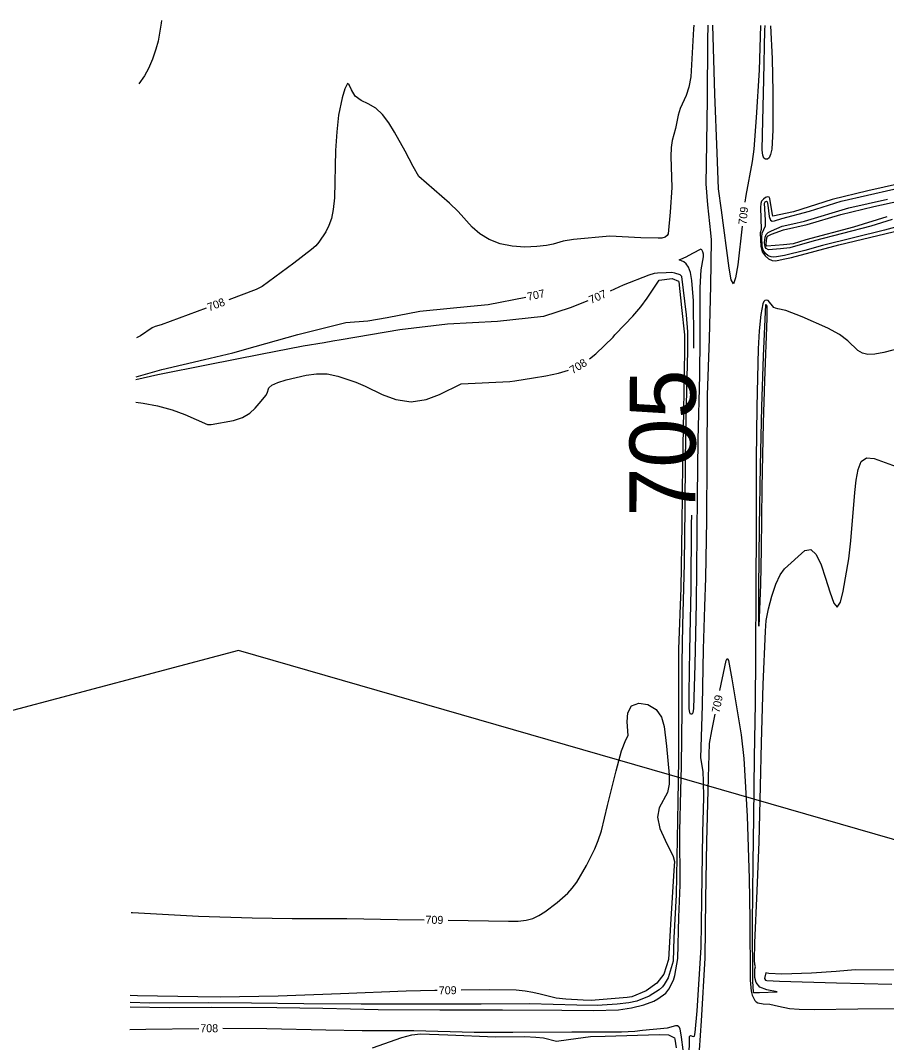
# Model space of a CAD drawing. Extents: x -468548933 to 3387700, y -306089263 to 1207014.
# Drawn here: x 1840205 to 1840637, y 538847 to 539357 of the extents above; entities that cross this region are included whole.
import ezdxf

# ---------------------------------------------------------------- set-up
doc = ezdxf.new("R2010")
doc.units = 0
for name, color, linetype in [('DT_X_Contour_Minor', 7, 'Continuous'), ('Level 19', 7, 'Continuous'), ('SC_Scratch1', 7, 'Continuous')]:
    doc.layers.add(name, color=color, linetype=linetype)

msp = doc.modelspace()

# ---------------------------------------------------------------- linework, layer by layer
at = {"layer": 'DT_X_Contour_Minor'}
for points in [[(1840275.27, 539357.39), (1840275.11, 539356.02), (1840273.58, 539347.09), (1840272.42, 539342.95), (1840270.74, 539337.98), (1840268.79, 539333.3), (1840266.8, 539329.74), (1840263.84, 539325.63)], [(1840541.08, 539355.09), (1840540.95, 539353.22), (1840539.56, 539329.22), (1840538.65, 539323.96), (1840537.24, 539319.82), (1840534.2, 539313.32), (1840533.25, 539310.01), (1840531.95, 539303.42), (1840530.29, 539297.44), (1840529.71, 539293.82), (1840529.58, 539289.35), (1840530.14, 539273.93), (1840529.32, 539261.5), (1840528.18, 539250.74), (1840527.67, 539249.86), (1840526.82, 539249.16), (1840525.11, 539248.62), (1840523.21, 539248.51), (1840514.65, 539248.83), (1840499.15, 539249.59), (1840480.99, 539247.95), (1840475.79, 539247.08), (1840470.81, 539245.57), (1840467.46, 539244.97), (1840462.6, 539244.4), (1840456.7, 539244.14), (1840450.42, 539244.53), (1840444.36, 539245.83), (1840438.85, 539247.97), (1840434.17, 539250.77), (1840430.44, 539254.1), (1840423.45, 539261.89), (1840419, 539266.08), (1840403.75, 539279.32), (1840400.96, 539284.32), (1840396.95, 539292.04), (1840391.55, 539301.57), (1840388.68, 539306.2), (1840385.64, 539310.3), (1840382.26, 539313.51), (1840378.51, 539315.67), (1840374.87, 539317.43), (1840371.94, 539319.61), (1840370.12, 539322.63), (1840369.03, 539325.25), (1840368.07, 539325.82), (1840366.82, 539323.26), (1840365.45, 539318.72), (1840363.59, 539310.13), (1840362.71, 539301.77), (1840362.2, 539292.44), (1840361.62, 539268.81), (1840361.03, 539262.84), (1840360.12, 539258.39), (1840358.86, 539254.83), (1840357.28, 539251.67), (1840353.88, 539246.64), (1840352.31, 539244.83), (1840350.19, 539242.89), (1840341.39, 539236.05), (1840325.52, 539224.36), (1840322.51, 539222.97), (1840308.82, 539217.81)], [(1840538.51, 538827.07), (1840538.9, 538849.64), (1840539.44, 538850.12), (1840540.81, 538849.55), (1840541.33, 538849.84), (1840541.75, 538851.59), (1840542.7, 538862.52), (1840544.67, 538894.15), (1840545.01, 538918.11), (1840545.62, 538951.61), (1840546, 538969), (1840545.97, 538976.98), (1840545.68, 538982.02), (1840544.62, 538988.9), (1840545.32, 539015.05), (1840545.86, 539043.18), (1840546.54, 539064.45), (1840547.04, 539078.86), (1840547.49, 539107.66), (1840547.77, 539138.03), (1840547.94, 539170.04), (1840548.81, 539198.39), (1840549.51, 539224.79), (1840549.88, 539247.75), (1840549.63, 539251.26), (1840548.07, 539265.28), (1840547.29, 539275.69), (1840547.32, 539285.61), (1840547.91, 539318.1), (1840548.11, 539347.54), (1840548.17, 539355.03)], [(1840565.19, 539254.65), (1840563.03, 539235.2), (1840561.93, 539228.72), (1840560.82, 539225.81), (1840559.74, 539227.82), (1840558.7, 539233.61), (1840554.89, 539262.6), (1840553.39, 539273.19), (1840552.64, 539291.27), (1840551.61, 539320.52), (1840550.6, 539355.01)], [(1840574.38, 539354.81), (1840573.69, 539332.46), (1840572.24, 539308.84), (1840571.04, 539293), (1840570.16, 539286.89), (1840566.97, 539269.97), (1840566.57, 539266.57)], [(1840579.32, 539354.76), (1840580.17, 539338.36), (1840580.53, 539321.56), (1840580.49, 539302.51), (1840579.98, 539293.1), (1840579.42, 539290.32), (1840578.69, 539288.8), (1840577.83, 539288.14), (1840576.92, 539288.05), (1840576.09, 539288.62), (1840575.49, 539290.07), (1840575.22, 539292.56), (1840575.32, 539300.46), (1840575.98, 539327.83), (1840576.59, 539352.53), (1840576.65, 539354.79)], [(1840652.47, 539277.8), (1840627.95, 539272.26), (1840610.13, 539267.92), (1840590.92, 539261.81), (1840580.47, 539259.64), (1840580.11, 539261.19), (1840579.08, 539268.33), (1840578.63, 539269.02), (1840577.92, 539269.2), (1840576.92, 539268.84), (1840575.83, 539268.07), (1840574.94, 539267.06), (1840574.45, 539265.96), (1840574.3, 539263.85), (1840574.67, 539252.92), (1840574.26, 539251.27), (1840574.28, 539247.52), (1840574.54, 539244.61), (1840575.27, 539241.82), (1840576.61, 539239.67), (1840578.36, 539238.24), (1840580.26, 539237.48), (1840582.05, 539237.32), (1840585.6, 539238.02), (1840589.78, 539239), (1840613.46, 539245.3), (1840644.74, 539252.76)], [(1840643.63, 539254.53), (1840636.34, 539252.58), (1840605.24, 539244.99), (1840596.46, 539242.47), (1840586.26, 539239.91), (1840582.33, 539239.28), (1840581.04, 539239.12), (1840579.64, 539239.25), (1840578.16, 539239.83), (1840576.8, 539240.94), (1840575.76, 539242.62), (1840575.19, 539244.79), (1840574.98, 539249.03), (1840575.13, 539251), (1840576.92, 539254.68), (1840576.83, 539257.58), (1840576.28, 539266.04), (1840576.69, 539266.73), (1840577.33, 539267.07), (1840577.68, 539266.81), (1840577.95, 539265.11), (1840578.76, 539259.33), (1840579.37, 539257.66), (1840580.23, 539257.06), (1840581.42, 539257.27), (1840584.98, 539258.47), (1840598.87, 539262.13), (1840614.59, 539266.99), (1840640.97, 539273.05)], [(1840640.05, 539257.86), (1840629.43, 539254.62), (1840601.21, 539247.32), (1840588.94, 539243.81), (1840584.27, 539243.28), (1840578.4, 539242.77), (1840577.18, 539243.5), (1840576.74, 539244.21), (1840576.42, 539246.23), (1840576.64, 539249.09), (1840577.2, 539250.43), (1840578.12, 539251.38), (1840579.83, 539252.22), (1840582.53, 539253.42), (1840585.17, 539254.58), (1840590.56, 539255.73), (1840596.36, 539257.11), (1840618.54, 539263.67), (1840637.79, 539268.09)], [(1840637.51, 539259.3), (1840620.72, 539254.15), (1840596.98, 539247.76), (1840590.6, 539245.81), (1840585.92, 539245.2), (1840577.57, 539244.62), (1840577.23, 539245.01), (1840577.13, 539245.8), (1840577.49, 539248.83), (1840577.91, 539249.63), (1840579.91, 539250.59), (1840585.88, 539252.8), (1840597.73, 539255.4), (1840614.53, 539260.48), (1840630.95, 539264.45), (1840643.96, 539267.23)], [(1840541.09, 539193.54), (1840541.11, 539198.23), (1840540.85, 539217.32), (1840540.07, 539227.39), (1840539.39, 539231.38), (1840538.43, 539234.14), (1840537.28, 539235.79), (1840536.07, 539236.7), (1840533.75, 539237.7), (1840534.62, 539238.16), (1840537.19, 539239.24), (1840540.62, 539241.06), (1840544.77, 539243.29), (1840545.4, 539241.9), (1840545.72, 539240.67), (1840545.8, 539239.28), (1840544.48, 539232.83), (1840544.1, 539223.92), (1840544.05, 539198.53), (1840543.83, 539180.17), (1840543.03, 539147.81), (1840542.73, 539119.66), (1840542.36, 539082.95), (1840542.18, 539066.32), (1840541.54, 539035.4), (1840540.91, 539013.5), (1840540.6, 539011.42), (1840540.22, 539010.66), (1840539.41, 539010.67), (1840539.05, 539011.43), (1840538.81, 539013.47), (1840538.74, 539021.39), (1840539.12, 539042.7), (1840539.66, 539073.16), (1840539.98, 539105.62), (1840539.99, 539110.23)], [(1840259.57, 538864.53), (1840279.11, 538864.1), (1840300.18, 538864.22), (1840332.91, 538864.04), (1840355.72, 538863.76), (1840383.5, 538863.11), (1840414.26, 538862.97), (1840445.56, 538862.89), (1840475.22, 538862.86), (1840490.97, 538862.62), (1840503.5, 538863.03), (1840509.98, 538863.93), (1840516.03, 538865.45), (1840521.05, 538867.27), (1840523.16, 538868.4), (1840527.1, 538871.36), (1840528.59, 538873.24), (1840530.93, 538877.72), (1840531.59, 538880.03), (1840533.12, 538888.58), (1840533.54, 538909.31), (1840534.25, 538925.28), (1840534.06, 538952.25), (1840534.65, 538972.49), (1840534.94, 538984.74), (1840535.26, 539012.92), (1840535.26, 539036.23), (1840535.61, 539055.22), (1840536.46, 539085.95), (1840536.76, 539113.5), (1840536.98, 539138.7), (1840537.47, 539165.37), (1840538.02, 539192.32), (1840538.01, 539201.84), (1840537.4, 539210.32), (1840535.11, 539229.37), (1840534.24, 539230.28), (1840531.52, 539231.17), (1840530.12, 539231.44), (1840527.24, 539231.27), (1840522.96, 539231.04), (1840521.19, 539230.95), (1840518.63, 539230.11), (1840505.8, 539225.04), (1840499.21, 539222.09)], [(1840488.99, 539188.27), (1840492.11, 539190.75), (1840500.84, 539199.04), (1840501.66, 539200.32), (1840506.53, 539205.48), (1840510.53, 539209.66), (1840514.53, 539214.24), (1840517.83, 539218.68), (1840523.68, 539227.66), (1840530.22, 539228.35), (1840533.42, 539227.03), (1840533.51, 539226.73), (1840534.92, 539214), (1840536.47, 539200.28), (1840536.48, 539192.29), (1840535.85, 539162.33), (1840535.42, 539136.08), (1840535.05, 539105.52), (1840534.52, 539073.76), (1840533.43, 539043.19), (1840533.43, 539018.18), (1840533.34, 538988.19), (1840533.05, 538966.99), (1840532.74, 538948.36), (1840532.21, 538920.34), (1840531.12, 538898.92), (1840530.72, 538887.2), (1840528.25, 538878.89), (1840526.31, 538875.69), (1840525.44, 538874.37), (1840523.73, 538872.87), (1840518.68, 538869.7), (1840512.57, 538867.36), (1840508.6, 538866.44), (1840502.81, 538865.81), (1840492.8, 538865.12), (1840482.63, 538865.23), (1840459.01, 538865.89), (1840434.85, 538865.81), (1840407.62, 538865.77), (1840375.02, 538865.72), (1840346.31, 538865.99), (1840320.16, 538866.33), (1840298.85, 538866.52), (1840269.49, 538866.21), (1840259.59, 538866.55)], [(1840488.21, 539217.28), (1840479.28, 539213.85), (1840465.97, 539209.45), (1840443.01, 539206.88), (1840418.12, 539205.68), (1840394.27, 539202.7), (1840364.88, 539197.82), (1840360.79, 539197.05), (1840356.44, 539196.26), (1840345.96, 539194.57), (1840324.59, 539190.42), (1840298.54, 539185.35), (1840273.39, 539180.36), (1840262.48, 539177.72)], [(1840262.5, 539179.22), (1840275.44, 539182.96), (1840296.72, 539188.01), (1840310.81, 539191.34), (1840321.99, 539194.41), (1840343.33, 539200.45), (1840367.27, 539206.37), (1840378.25, 539207.33), (1840387.98, 539208.97), (1840404.28, 539212.15), (1840405.84, 539212.34), (1840429.48, 539214.61), (1840438.36, 539215.48), (1840457.11, 539219.16)], [(1840648.82, 539194.75), (1840635.93, 539191.42), (1840631.41, 539190.59), (1840627.91, 539190.46), (1840625.24, 539191.1), (1840623.03, 539192.51), (1840617.99, 539197.35), (1840613.82, 539200.41), (1840607.94, 539203.61), (1840595.1, 539209.25), (1840587.01, 539212.38), (1840582.99, 539213.35), (1840581.82, 539213.53), (1840580.96, 539213.95), (1840578.14, 539217.4), (1840577.31, 539217.53), (1840576.57, 539217.35), (1840575.99, 539216.87), (1840575.53, 539215.79), (1840574.6, 539210.45), (1840573.73, 539202.26), (1840573.24, 539193.28), (1840572.54, 539164.32), (1840572.14, 539137.98), (1840572.14, 539103.4), (1840571.99, 539074.52), (1840571.8, 539039.53), (1840571.64, 539016.12), (1840571.27, 538989.29), (1840570.93, 538959.05), (1840570.6, 538936.51), (1840570.21, 538906.01), (1840570.33, 538877.2), (1840570.72, 538871.75), (1840570.89, 538871.68), (1840573.81, 538871.66), (1840582.62, 538872.01), (1840577.58, 538872.93), (1840574.1, 538874.29), (1840572.14, 538876.54), (1840571.46, 538879.12), (1840571.54, 538883.25), (1840571.91, 538884.51), (1840571.56, 538885.68), (1840571.42, 538887.79), (1840571.6, 538896.44), (1840572.7, 538922.49), (1840573.72, 538946.95), (1840574.35, 538974.69), (1840574.78, 538996.4), (1840575.77, 539025.61), (1840576.78, 539052.15), (1840577.27, 539057.44), (1840578.28, 539063.42), (1840579.95, 539069.74), (1840582.06, 539075.65), (1840584.26, 539080.33), (1840586.33, 539083.26), (1840596.55, 539092.57), (1840599.52, 539093.08), (1840602.21, 539090.49), (1840604.65, 539085.37), (1840606.89, 539078.74), (1840608.97, 539071.76), (1840610.91, 539066.23), (1840612.69, 539064.1), (1840614.3, 539066.63), (1840615.72, 539072.2), (1840618.52, 539088.25), (1840619.54, 539097.37), (1840621.47, 539121.52), (1840622.18, 539127.65), (1840623.12, 539132.99), (1840624.67, 539136.93), (1840627.28, 539138.88), (1840631.19, 539138.53), (1840644.02, 539133.74)], [(1840574.44, 539075.49), (1840573.5, 539054.69), (1840573.52, 539073.49), (1840573.89, 539104.49), (1840574.3, 539134.78), (1840574.99, 539164.23), (1840575.79, 539189.53), (1840577, 539215.36), (1840577.26, 539215.39), (1840577.49, 539214.81), (1840577.47, 539208.62), (1840576.3, 539177.23), (1840575.65, 539156.38), (1840574.98, 539123.88), (1840574.63, 539093.1), (1840574.44, 539075.49)], [(1840297.59, 539213.6), (1840275, 539205.21), (1840272.03, 539204.5), (1840270.6, 539203.82), (1840264.74, 539199.79), (1840262.68, 539198.75)], [(1840262.38, 539166.66), (1840266.15, 539166.1), (1840273.21, 539164.77), (1840280.48, 539162.87), (1840286.87, 539160.48), (1840298.15, 539155.49), (1840300.05, 539155.49), (1840311.19, 539157.42), (1840315.75, 539158.92), (1840319.39, 539161.13), (1840322.03, 539163.56), (1840325.01, 539167.16), (1840327.3, 539169.89), (1840327.96, 539171.19), (1840328.76, 539173.77), (1840330.26, 539175.09), (1840333.3, 539176.45), (1840337.54, 539177.81), (1840347.44, 539180.2), (1840352.6, 539180.86), (1840357.92, 539180.75), (1840363.34, 539179.7), (1840372.26, 539176.68), (1840377.02, 539174.69), (1840385.5, 539170.5), (1840392.32, 539167.98), (1840399.87, 539166.84), (1840407.35, 539167.98), (1840414, 539170.51), (1840424.95, 539175.8), (1840449.13, 539176.98), (1840451.73, 539177.33), (1840461.05, 539178.73), (1840467.22, 539179.74), (1840473.51, 539181.07), (1840478.41, 539182.57)], [(1840554.1, 539022.53), (1840556.47, 539034.34), (1840557.25, 539037.56), (1840557.79, 539038.52), (1840558.3, 539037.54), (1840560.01, 539028.3), (1840564.62, 539000.44), (1840565.97, 538988.59), (1840567.63, 538959.69), (1840568.65, 538928.53), (1840569, 538908.04), (1840569.2, 538877.84), (1840569.7, 538872.31), (1840570.17, 538870.21), (1840571.45, 538867.62), (1840572.19, 538866.88), (1840573.08, 538866.41), (1840575.75, 538866.02), (1840579.1, 538865.8), (1840583.32, 538864.79), (1840588.88, 538863.69), (1840593.69, 538863.21), (1840601.18, 538863.13), (1840622.98, 538863.48), (1840652.3, 538863.58)], [(1840418.32, 538907.84), (1840448.54, 538907.26), (1840453.42, 538907.3), (1840457.28, 538907.71), (1840460.59, 538908.61), (1840463.64, 538910.02), (1840466.65, 538911.9), (1840472.86, 538916.66), (1840478.11, 538921.3), (1840480.32, 538923.67), (1840482.57, 538926.68), (1840487.52, 538935.11), (1840491.7, 538943.47), (1840493.33, 538947.52), (1840494.88, 538952.44), (1840497.99, 538965.02), (1840502.22, 538982.46), (1840504.89, 538992.4), (1840507.11, 538997.94), (1840508.35, 539000), (1840507.78, 539006.94), (1840508.13, 539011.36), (1840509.91, 539014.85), (1840513.59, 539016.22), (1840518.16, 539015.51), (1840522.28, 539013.06), (1840524.91, 539009.25), (1840526.29, 539004.58), (1840527.49, 538994.72), (1840528.8, 538980.44), (1840528.79, 538975.79), (1840527.87, 538971.52), (1840523.71, 538963.83), (1840522.85, 538959.24), (1840524.16, 538953.58), (1840526.75, 538947.68), (1840530.73, 538939.52), (1840531.33, 538937.06), (1840531.07, 538932.63), (1840529.44, 538905.6), (1840528.49, 538888.1), (1840526.13, 538880.85), (1840522.6, 538876.21), (1840517.2, 538872.45), (1840510.15, 538869.53), (1840507.84, 538869.15), (1840489.88, 538867.6), (1840485.84, 538867.71), (1840477.13, 538868.21), (1840472.27, 538868.81), (1840464.33, 538870.75), (1840460.74, 538871.69), (1840456.92, 538872.35), (1840452.36, 538872.74), (1840439.26, 538872.92), (1840424.95, 538872.79)], [(1840543.82, 538842.74), (1840544.85, 538857.51), (1840546.65, 538888.73), (1840547.07, 538918.46), (1840547.56, 538946.96), (1840548.36, 538979), (1840548.85, 538996.07), (1840550.05, 539002.35), (1840551.74, 539010.77)], [(1840260.01, 538911.59), (1840260.78, 538911.52), (1840293.67, 538909.79), (1840320.58, 538908.97), (1840340.48, 538908.54), (1840367.8, 538908.63), (1840393.01, 538908.13), (1840406.32, 538907.98)], [(1840653.2, 538882.84), (1840621.69, 538882.88), (1840612.08, 538882.17), (1840599.77, 538881.27), (1840584.95, 538880.84), (1840578.51, 538881.14), (1840576.98, 538881.38), (1840576.42, 538878.56), (1840576.8, 538877.77), (1840577.54, 538877.57), (1840583.83, 538877.3), (1840612.34, 538876.51), (1840639.89, 538875.83)], [(1840412.95, 538872.69), (1840411.74, 538872.68), (1840397.44, 538872.34), (1840364.68, 538870.99), (1840333.55, 538869.82), (1840304.51, 538869.36), (1840293.38, 538869.38), (1840263.33, 538870.02), (1840259.62, 538870.09)], [(1840259.47, 538853.09), (1840267.34, 538853.32), (1840293.84, 538853.69)], [(1840305.84, 538853.72), (1840327.84, 538853.59), (1840357.3, 538852.99), (1840375.47, 538852.68), (1840401.16, 538852.64), (1840431.32, 538851.76), (1840450.62, 538851.73), (1840480.18, 538851.91), (1840504.9, 538851.96), (1840511.62, 538852.31), (1840515.5, 538852.87), (1840527.88, 538854.02), (1840532.02, 538855.1), (1840532.97, 538855.1), (1840533.61, 538854.62), (1840534.07, 538853.45), (1840534.81, 538849.3), (1840535.6, 538843.03)], [(1840380.52, 538843.89), (1840395.29, 538849.16), (1840400.27, 538850.51), (1840404.63, 538850.96), (1840418.17, 538850.51), (1840442.04, 538849.49), (1840456.73, 538849.55), (1840462.24, 538849.34), (1840466.03, 538848.89), (1840472.53, 538847.36), (1840478.46, 538848.1), (1840489.46, 538849.6), (1840496.77, 538849.77), (1840523.83, 538850.57), (1840528.48, 538850.51), (1840531.36, 538848.93), (1840531.64, 538848.32), (1840532.26, 538843.97)]]:
    msp.add_lwpolyline(points, dxfattribs=at)
at = {"layer": 'SC_Scratch1'}
msp.add_lwpolyline([(1834448.38, 536360.46), (1835055.83, 534489.39), (1836664.2, 534206.16), (1839225.76, 534394.17), (1842361.7, 536308.3), (1842189.37, 536805.14), (1841581.79, 538676.58), (1840313.7, 539042.49), (1837357.67, 538260.17), (1834781.04, 538194.31), (1834403.13, 536496.43)], close=True, dxfattribs=at)

# ---------------------------------------------------------------- texts
at = {"layer": 'Level 19'}
for s, height, rotation, p in [('709', 4, 83.3023, (1840567.24, 539255.15)), ('707', 4, 11.8029, (1840458.25, 539217.33)), ('707', 4, 24.1387, (1840489.75, 539215.66)), ('708', 4, 20.6666, (1840299.01, 539211.98)), ('708', 4, 31.8049, (1840480.56, 539180.53)), ('705', 33, 89.7596, (1840541.82, 539109.28)), ('709', 4, 78.6614, (1840553.85, 539011.1)), ('709', 4, 359.3649, (1840407.04, 538905.97)), ('709', 4, 0.5042, (1840413.71, 538870.69)), ('708', 4, 359.6456, (1840294.58, 538851.79))]:
    msp.add_text(s, height=height, rotation=rotation, dxfattribs=at).set_placement(p)

doc.saveas('drawing.dxf')
